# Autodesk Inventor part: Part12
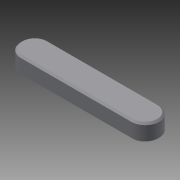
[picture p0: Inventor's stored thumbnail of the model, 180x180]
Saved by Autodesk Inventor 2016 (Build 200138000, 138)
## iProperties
Created: 2015-03
Part Number: Part12
Material: Generic
Document SubType Name: Modeling
Designer: Uglješa
Density: 1 g/cm^3
Appearance: Default
Mass: 0.719306 g
Surface Area: 5.08763 cm^2
Volume: 0.719306 cm^3
Author: Uglješa
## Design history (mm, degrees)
sketch "Sketch1"
  geometry: L1 (6.5, 0)-(18.5, 0) reference; L2 (6.5, -8)-(18.5, -8) reference; A1 r 4 centre (6.5, -4) between (6.5, 0) and (6.5, -8) reference; A2 r 4 centre (18.5, -4) between (18.5, -8) and (18.5, 0) reference; 1 further point
extrude "Extrusion1" new body sketch "Sketch1" distance "d3" = 5; taper "d4" = 0 deg
chamfer "Chamfer1" distance "d5" = 0.5; stored, may be unused: second distance "d6" = 2, angle "d7" = 45 deg
body "Solid1"
node "Reference1"
